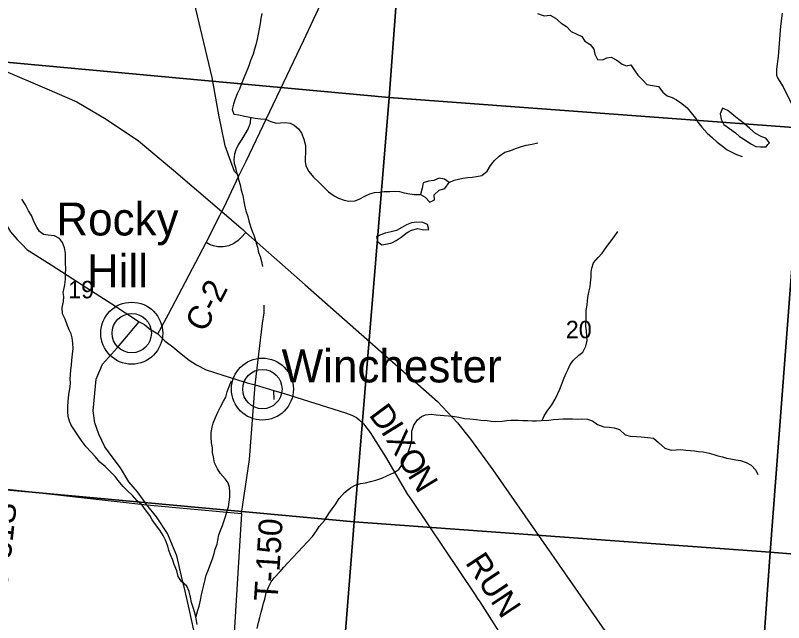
# Model space of a CAD drawing. Extents: x 1715311 to 2083412, y 146837 to 553079.
# Drawn here: x 1954235 to 1963973, y 356508 to 364200 of the extents above; entities that cross this region are included whole.
import ezdxf

# ---------------------------------------------------------------- set-up
doc = ezdxf.new("R2010")
doc.units = 0
for name, color, linetype in [('GM_X_County_Road', 7, 'Continuous'), ('GM_X_County_Road_Text', 7, 'Continuous'), ('GM_X_Minor_Lake', 7, 'Continuous'), ('GM_X_Minor_River', 7, 'Continuous'), ('GM_X_Section', 7, 'Continuous'), ('GM_X_Section_Text', 7, 'Continuous'), ('GM_X_State_Route', 7, 'Continuous'), ('GM_X_Township_Road', 7, 'Continuous'), ('GM_X_Township_Road_Text', 7, 'Continuous'), ('GM_X_Township_ROW', 7, 'Continuous'), ('GM_X_Township_Subdivision', 7, 'Continuous'), ('GM_X_Unincorporated', 7, 'Continuous'), ('GM_X_Unincorporated_Location', 7, 'Continuous'), ('GM_X_Unincorporated_Text', 7, 'Continuous'), ('GM_X_US_Route', 7, 'Continuous')]:
    doc.layers.add(name, color=color, linetype=linetype)

msp = doc.modelspace()

# ---------------------------------------------------------------- linework, layer by layer
at = {"layer": 'GM_X_County_Road'}
for points in [[(1953324, 363823.9), (1953334.1, 363699.1), (1953343.2, 363599.2), (1953386.3, 363492.5), (1953440.8, 363394.8), (1953482.8, 363304), (1953627.9, 362731.6), (1953678, 362472.8), (1953734.7, 362326), (1954079.4, 361615.9), (1954175, 361456.6), (1954259.1, 361358.7), (1954329.7, 361290.4), (1954382, 361233.5), (1954689.1, 361040.1), (1955096.4, 360778.3), (1955455.9, 360546.2), (1955806.2, 360315.7)], [(1956041.5, 360166.1), (1956175.7, 360414.7), (1956652.1, 361322.2)], [(1956496.9, 356413.5), (1956435.8, 356683.5), (1956388.9, 356905.5), (1956342.2, 357095.5), (1956283.2, 357353.5), (1956162.1, 357635.2), (1956025.4, 357848.8), (1955900.2, 358001.2), (1955782.3, 358163.9), (1955673.9, 358289.5), (1955567.3, 358467.2), (1955462.9, 358608.9), (1955370.4, 358736.5), (1955293.8, 358894.3), (1955243.3, 359040.2), (1955220.7, 359190.3), (1955260.9, 359590.9), (1955338, 359781.5), (1955528.9, 359994.7), (1955806.2, 360315.7)], [(1955806.2, 360315.7), (1955870, 360282.7), (1955936, 360227.7), (1956041.5, 360166.1)], [(1956041.5, 360166.1), (1956133.9, 360071.6), (1956232.9, 359999), (1956338.4, 359913.2), (1956439.6, 359834), (1956531.9, 359774.5), (1956655.1, 359710.8), (1957048.8, 359583.1), (1957174.1, 359543.5), (1957275.3, 359519.4), (1957509.3, 359448.8), (1957640.4, 359409.4), (1958420.2, 359165.6), (1958501.2, 359136.5), (1958557.8, 359104), (1958593.5, 359074.9), (1958646.9, 359026.3), (1958731.1, 358916.2), (1958927, 358606.8), (1959206.2, 358129.1), (1959222.5, 358108), (1959266.6, 358042.4), (1960062.6, 356859.4), (1960089.4, 356819.1), (1960120.3, 356770.8), (1960802.6, 355702.6)], [(1955900.2, 358001.2), (1957100.4, 357888.1), (1957201, 358574.4), (1957275.3, 359519.4)], [(1953288.4, 358290.3), (1953525.5, 358265.5), (1953751.8, 358240.9), (1955900.2, 358001.2)]]:
    msp.add_lwpolyline(points, dxfattribs=at)
at = {"layer": 'GM_X_Minor_Lake'}
for points in [[(1963197.6, 363024.8), (1963167.7, 362950.7), (1963179.7, 362884.6), (1963215.6, 362818.6), (1963285.5, 362768.6), (1963361.3, 362712.6), (1963415.1, 362666.6), (1963488.9, 362620.6), (1963554.8, 362574.5), (1963618.6, 362540.5), (1963680.4, 362534.5), (1963750.2, 362534.6), (1963773.5, 362563.4)], [(1963773.5, 362563.4), (1963792.1, 362586.6), (1963748.2, 362644.6), (1963696.3, 362662.6), (1963616.5, 362702.6), (1963544.7, 362766.7), (1963476.9, 362824.7), (1963405.1, 362878.7), (1963339.2, 362932.7), (1963263.4, 362994.8), (1963197.6, 363024.8)], [(1959734.9, 362082.2), (1959672.2, 362125.2), (1959606.4, 362137.1), (1959540.6, 362109.1), (1959470.8, 362099.1), (1959403, 362079.1), (1959393.1, 362011), (1959371, 361929.7)], [(1959371, 361929.7), (1959428.7, 361897.4), (1959488.3, 361835.1), (1959546.3, 361864.8), (1959544.6, 361926.9), (1959604.7, 361986.7), (1959676.7, 362008.4), (1959734.9, 362082.2)], [(1959209.8, 361451.7), (1959257.7, 361478.6), (1959335.5, 361500.6), (1959407.3, 361484.6), (1959475.1, 361486.7), (1959459.1, 361550.7), (1959401.2, 361576.7), (1959325.5, 361580.7), (1959257.7, 361570.7), (1959191.9, 361546.6), (1959134, 361512.6), (1959064.3, 361474.5), (1958998.5, 361456.5), (1958920.7, 361442.5), (1958813, 361398.4)], [(1958813, 361398.4), (1958823, 361334.4), (1958880.9, 361292.4), (1958950.7, 361304.4), (1959004.5, 361318.4), (1959062.3, 361346.5), (1959136.1, 361400.5), (1959189.9, 361440.6), (1959209.8, 361451.7)]]:
    msp.add_lwpolyline(points, dxfattribs=at)
at = {"layer": 'GM_X_Minor_River'}
for points in [[(1957357.5, 364225.2), (1957345.2, 364158.6), (1957338.9, 364096.6), (1957324.6, 364028.6), (1957314.4, 363960.6), (1957300.1, 363896.6), (1957281.9, 363828.6), (1957265.7, 363770.6), (1957249.4, 363708.7), (1957213.2, 363626.8), (1957197, 363572.8), (1957176.8, 363518.9), (1957154.6, 363466.9), (1957130.4, 363409), (1957096.1, 363325.1), (1957073.9, 363265.1), (1957047.7, 363207.2), (1957017.4, 363129.3), (1957001.2, 363075.3), (1956981, 363005.3), (1957002.7, 362947.2), (1957066.5, 362938.9), (1957138.3, 362924.6), (1957208.1, 362908.2), (1957273.9, 362897.9), (1957343.7, 362889.6), (1957403.5, 362883.3), (1957471.2, 362857), (1957539, 362832.7), (1957594.9, 362836.4), (1957652.8, 362842.2), (1957718.6, 362833.9), (1957770.4, 362807.6), (1957822.1, 362763.3), (1957859.7, 362709.1), (1957893.3, 362630.9), (1957912.9, 362552.8), (1957910.7, 362500.7), (1957910.1, 362350.6), (1957917.8, 362294.5), (1957953.4, 362220.3), (1958013, 362152), (1958078.6, 362089.6), (1958138.2, 362033.3), (1958203.7, 361963), (1958275.4, 361914.6), (1958331.1, 361884.3), (1958402.8, 361858), (1958460.7, 361845.7), (1958542.5, 361849.4), (1958602.5, 361877.1), (1958664.5, 361908.9), (1958726.5, 361938.6), (1958788.4, 361954.3), (1958856.3, 361962), (1958908.2, 361967.8), (1958982, 361969.5), (1959045.9, 361971.2), (1959105.8, 361966.9), (1959163.6, 361952.6), (1959233.4, 361938.3), (1959295.2, 361930), (1959371, 361929.7), (1959428.7, 361897.4), (1959488.3, 361835.1), (1959546.3, 361864.8), (1959544.6, 361926.9), (1959604.7, 361986.7), (1959676.7, 362008.4), (1959734.9, 362082.2), (1959794.9, 362111.9), (1959850.8, 362123.7), (1959906.7, 362137.4), (1959966.6, 362147.2), (1960026.5, 362150.9), (1960080.4, 362156.6), (1960148.3, 362170.4), (1960216.4, 362228.1), (1960258.6, 362300), (1960308.8, 362361.8), (1960368.9, 362417.5), (1960439, 362465.3), (1960514.9, 362489), (1960574.9, 362512.7), (1960636.8, 362536.4), (1960710.7, 362554.1), (1960784.7, 362569.8), (1960856.6, 362583.5)], [(1960851.8, 364222.7), (1960939.3, 364194.4), (1961015.2, 364204), (1961082.9, 364165.7), (1961152.5, 364099.3), (1961222.1, 364057), (1961279.7, 363996.7), (1961351.4, 363960.3), (1961415.2, 363934), (1961452.8, 363871.8), (1961520.5, 363831.5), (1961568.1, 363771.2), (1961579.8, 363707.1), (1961615.4, 363638.9), (1961681.3, 363638.6), (1961733.3, 363660.3), (1961787.2, 363670.1), (1961858.9, 363631.8), (1961926.5, 363581.4), (1961980.3, 363561.1), (1962034.2, 363574.9), (1962079.9, 363510.7), (1962125.5, 363442.4), (1962183.1, 363382.1), (1962240.7, 363323.8), (1962310.5, 363309.5), (1962386.3, 363297.1), (1962441.8, 363228.8), (1962497.5, 363178.5), (1962561.3, 363160.2), (1962613, 363129.9), (1962680.7, 363081.6), (1962748.3, 363029.3), (1962801.9, 362965), (1962855.5, 362896.7), (1962883.2, 362846.5), (1962936.8, 362782.2), (1963004.3, 362705.8), (1963071.9, 362647.5), (1963131.6, 362595.2), (1963197.2, 362542.8), (1963256.9, 362496.5), (1963308.6, 362470.3), (1963374.3, 362436), (1963446.1, 362411.6)], [(1957216.6, 362906.9), (1957211.7, 362832.2), (1957187.5, 362766.2), (1957143.3, 362696.3), (1957105.1, 362632.5), (1957056.9, 362560.6), (1957030.7, 362494.7), (1957014.5, 362442.7), (1957002.2, 362374.7), (1957010, 362324.7), (1957023.7, 362274.6), (1957033.5, 362224.5), (1957049.2, 362174.4), (1957065, 362122.3), (1957082.6, 362052.1), (1957098.3, 361984), (1957118, 361917.8), (1957131.6, 361841.7), (1957145.3, 361775.6), (1957155, 361723.5), (1957180.7, 361651.4), (1957194.4, 361595.2), (1957216, 361525.1), (1957235.8, 361467), (1957257.5, 361416.8), (1957273.2, 361364.7), (1957289, 361314.6), (1957302.7, 361262.5), (1957318.4, 361196.4), (1957336.1, 361144.3), (1957353.8, 361080.1), (1957367.5, 361020)], [(1954401.3, 361723.8), (1954361.7, 361798.1), (1954318.1, 361870.3)], [(1956539.8, 356484.1), (1956528.1, 356554.2), (1956514.4, 356616.4), (1956490.7, 356686.5), (1956469.1, 356762.7), (1956453.4, 356830.8), (1956435.8, 356900.9), (1956410.1, 356969.1), (1956340.6, 357029.5), (1956298.9, 357091.7), (1956281.3, 357163.8), (1956249.7, 357242), (1956230, 357298.2), (1956202.3, 357368.4), (1956180.6, 357424.5), (1956166.9, 357476.6), (1956137.3, 357550.8), (1956109.6, 357611), (1956066, 357679.2), (1956012.4, 357749.5), (1955970.8, 357811.8), (1955939.1, 357865.9), (1955885.5, 357936.2), (1955841.9, 357994.5), (1955778.2, 358050.8), (1955720.7, 358119.1), (1955651.1, 358181.5), (1955603.4, 358231.7), (1955537.9, 358308.1), (1955500.2, 358358.3), (1955432.6, 358426.6), (1955375, 358487), (1955307.4, 358541.3), (1955251.8, 358607.6), (1955192.2, 358671.9), (1955130.7, 358736.2), (1955067.2, 358818.6), (1954976, 358957.1), (1954940.3, 359009.3), (1954920.6, 359061.4), (1954902.8, 359119.6), (1954899.1, 359181.6), (1954901.4, 359247.7), (1954905.6, 359305.7), (1954909.9, 359359.7), (1954918.1, 359423.7), (1954928.4, 359493.7), (1954932.6, 359543.8), (1954930.8, 359593.8), (1954933.1, 359645.8), (1954939.3, 359707.9), (1954947.6, 359769.9), (1954951.8, 359833.9), (1954960.1, 359909.9), (1954966.4, 359978), (1954964.7, 360048), (1954953, 360114.1), (1954941.3, 360164.2), (1954915.6, 360218.4), (1954891.9, 360280.5), (1954866.3, 360350.7), (1954832.6, 360420.9), (1954829, 360501), (1954843.3, 360577), (1954847.5, 360637), (1954841.8, 360691.1), (1954858.1, 360765.1), (1954864.3, 360817.1), (1954870.5, 360867.1), (1954870.7, 360927.1), (1954873, 360989.2), (1954871.3, 361065.2), (1954871.6, 361133.3), (1954869.9, 361187.3), (1954858.2, 361255.5), (1954834.5, 361321.6), (1954794.8, 361371.8), (1954731.1, 361408.1), (1954651.3, 361414.5), (1954591.5, 361424.8), (1954539.8, 361463), (1954508.1, 361515.2), (1954474.5, 361579.4), (1954438.9, 361663.6), (1954401.3, 361723.8)], [(1960912.5, 359067.4), (1960935.4, 359126.4), (1960983.6, 359198.2), (1961035.8, 359268), (1961078, 359339.9), (1961110.2, 359409.8), (1961134.4, 359465.8), (1961164.7, 359539.7), (1961192.9, 359609.6), (1961217.1, 359665.5), (1961241.3, 359717.5), (1961267.5, 359777.4), (1961309.6, 359831.2), (1961377.8, 359897), (1961427.8, 359932.8), (1961466, 360008.7), (1961480.3, 360082.7), (1961476.6, 360138.7), (1961472.9, 360202.8), (1961467.1, 360262.9), (1961467.7, 360389), (1961470, 360461), (1961480.3, 360531), (1961486.5, 360587), (1961494.8, 360651), (1961507, 360709), (1961519.2, 360761), (1961525.4, 360813), (1961533.7, 360889.1), (1961534, 360947.1), (1961540.2, 360999.1), (1961564.4, 361067.1), (1961620.6, 361130.9), (1961672.7, 361188.7), (1961722.9, 361258.5), (1961771.1, 361324.3), (1961823.3, 361394.1), (1961871.4, 361460)], [(1956523.6, 356574.4), (1956546.5, 356666.3), (1956564.7, 356718.2), (1956581, 356794.2), (1956595.2, 356858.2), (1956605.5, 356914.2), (1956621.7, 356984.2), (1956640, 357052.1), (1956654.2, 357110.1), (1956684.4, 357182), (1956712.7, 357260), (1956732.9, 357315.9), (1956753.2, 357381.9), (1956769.4, 357439.9), (1956793.6, 357501.8), (1956799.8, 357551.8), (1956814, 357617.8), (1956834.2, 357675.8), (1956860.5, 357739.7), (1956898.9, 357853.6), (1956921.1, 357923.6), (1956937.3, 357975.5), (1956945.6, 358035.5), (1956953.8, 358101.6), (1956954.1, 358163.6), (1956948.3, 358217.7), (1956930.6, 358277.8), (1956892.9, 358328), (1956831.4, 358402.3), (1956795.7, 358454.6), (1956760.1, 358532.8), (1956746.5, 358606.9), (1956734.7, 358661), (1956733, 358721), (1956721.3, 358785.1), (1956715.6, 358855.2), (1956715.9, 358915.3), (1956730.1, 358983.3), (1956742.3, 359035.2), (1956770.6, 359105.2), (1956806.8, 359183.1), (1956833, 359241), (1956871.2, 359310.9), (1956901.4, 359362.8), (1956921.6, 359430.8), (1956943.9, 359500.7), (1956976.1, 359568.6)], [(1957301.8, 356434.7), (1957316.1, 356508.7), (1957334.3, 356570.6), (1957348.6, 356640.6), (1957366.8, 356698.6), (1957381, 356752.6), (1957397.2, 356804.5), (1957415.5, 356886.5), (1957443.8, 356956.5), (1957478, 357022.3), (1957516.1, 357076.2), (1957590.3, 357156), (1957636.4, 357209.8), (1957688.6, 357265.6), (1957752.7, 357331.3), (1957816.9, 357399.1), (1957875, 357462.9), (1957937.2, 357530.7), (1957999.3, 357600.5), (1958051.5, 357672.3), (1958083.7, 357724.2), (1958153.8, 357801.9), (1958210.1, 357889.7), (1958248.3, 357947.6), (1958290.4, 358001.5), (1958338.6, 358079.3), (1958406.8, 358155), (1958482.9, 358216.8), (1958542.9, 358250.5), (1958608.9, 358268.2), (1958674.7, 358277.9), (1958734.7, 358295.7), (1958802.6, 358311.4), (1958878.6, 358339.1), (1958952.5, 358370.8), (1959028.5, 358406.4), (1959096.5, 358446.2), (1959138.7, 358512), (1959166.9, 358563.9), (1959205.1, 358633.8), (1959227.3, 358699.8), (1959243.5, 358751.7), (1959259.8, 358821.7), (1959258, 358877.8), (1959260.3, 358931.8), (1959284.6, 359009.8), (1959330.8, 359077.6), (1959382.8, 359119.4), (1959434.8, 359141.2), (1959506.7, 359148.9), (1959570.5, 359140.6), (1959668.2, 359130.1), (1959724.1, 359127.9), (1959776, 359121.6), (1959855.7, 359111.3), (1959929.5, 359094.9), (1959997.3, 359090.6), (1960081.1, 359082.2), (1960135, 359074), (1960214.8, 359069.6), (1960266.6, 359059.3), (1960324.4, 359055.1), (1960404.3, 359060.7), (1960464.2, 359068.5), (1960516.1, 359074.2), (1960607.9, 359073.8), (1960665.8, 359069.6), (1960729.6, 359067.3), (1960785.5, 359065), (1960841.4, 359064.8), (1960901.2, 359066.5), (1960995.1, 359074.1), (1961051, 359081.8), (1961118.8, 359085.5), (1961178.7, 359089.2), (1961234.6, 359091), (1961294.4, 359088.7), (1961358.3, 359086.4), (1961410.2, 359088.2), (1961488, 359085.8), (1961549.8, 359065.5), (1961613.4, 359019.2), (1961693.1, 358988.8), (1961761, 358984.5), (1961824.8, 358976.2), (1961892.5, 358951.9), (1961964.1, 358887.5), (1962027.9, 358871.2), (1962107.7, 358864.9), (1962167.5, 358860.6), (1962249.3, 358854.2), (1962321.1, 358843.9), (1962386.7, 358787.5)], [(1962386.7, 358787.5), (1962468.3, 358719.1), (1962546, 358692.7), (1962609.8, 358696.5), (1962665.7, 358700.2), (1962733.6, 358693.9), (1962789.4, 358687.6), (1962841.3, 358683.4), (1962893.1, 358677.1), (1962953, 358672.9), (1963030.7, 358652.5), (1963088.5, 358638.2), (1963140.3, 358622), (1963196.1, 358605.7), (1963250, 358591.5), (1963303.8, 358581.2), (1963365.6, 358570.9), (1963425.4, 358560.6), (1963499.2, 358536.3), (1963562.9, 358504), (1963620.5, 358437.7), (1963646.2, 358383.5)]]:
    msp.add_lwpolyline(points, dxfattribs=at)
at = {"layer": 'GM_X_Section'}
for points in [[(1952754.9, 369183.8), (1959375.5, 368573.3), (1958974.7, 363158.1), (1952234.1, 363778.4), (1952509.1, 366607.6)], [(1959375.5, 368573.3), (1964620, 368129.6), (1964211.2, 362770.7), (1958974.7, 363158.1)], [(1952234.1, 363778.4), (1958974.7, 363158.1), (1958529.2, 357783.6), (1951688.6, 358412.1), (1951966.4, 361232.3)], [(1958974.7, 363158.1), (1964211.2, 362770.7), (1963799.8, 357398.1), (1958529.2, 357783.6)], [(1964211.2, 362770.7), (1969556.4, 362397.9), (1969150.3, 356964.7), (1963799.8, 357398.1)], [(1958529.2, 357783.6), (1958107.7, 352465.1), (1951153, 353047.6), (1951386.6, 355501.9), (1951688.6, 358412.1)], [(1963799.8, 357398.1), (1963420.2, 352039.6), (1958107.7, 352465.1), (1958529.2, 357783.6)], [(1963799.8, 357398.1), (1969150.3, 356964.7), (1968750.1, 351653.6), (1963420.2, 352039.6)]]:
    msp.add_lwpolyline(points, close=True, dxfattribs=at)
at = {"layer": 'GM_X_State_Route'}
for points in [[(1957158.9, 362353.6), (1957891.4, 363887.2), (1958316.8, 364800.5), (1958792.8, 365787)], [(1956660.6, 361339.3), (1956824.5, 361665.9), (1956852.8, 361715.4), (1956879.7, 361771.9), (1957069.1, 362165.6), (1957158.9, 362353.6)], [(1957154.3, 361451.1), (1957097.4, 361384.5), (1957059.2, 361347.7), (1957002.6, 361308.1), (1956941.9, 361281.2), (1956869.8, 361267.1), (1956803.3, 361269.9), (1956745.4, 361281.2), (1956704.4, 361294), (1956652.1, 361322.2), (1956660.6, 361339.3)]]:
    msp.add_lwpolyline(points, dxfattribs=at)
at = {"layer": 'GM_X_Township_Road'}
for points in [[(1963953.6, 364227.3), (1963934.5, 364064), (1963904.7, 363679), (1963883.2, 363516.9), (1963882, 363471.5), (1963883.2, 363444.2), (1963895.2, 363407.2), (1963966.6, 363296.3), (1964094.2, 363037.7)], [(1957069.1, 362165.6), (1957011.9, 362222.7), (1956965.1, 362350.1), (1956894.4, 362546.3), (1956837.8, 362815.4), (1956819.9, 362912.5)], [(1957275.3, 359519.4), (1957365.4, 360298.1), (1957387.5, 360432.3), (1957389.7, 360526.9)], [(1957100.4, 357888.1), (1956997.3, 356169.6), (1957184.3, 355870.2), (1957399.3, 355585), (1957521.8, 355433.4), (1957660.2, 355289.9), (1958014.6, 355095.4), (1958535.3, 354771.5), (1959068, 354455.8), (1959698.8, 354074.4), (1960199.6, 353752.4), (1960538, 353553.8), (1960710.2, 353462.5), (1960966.9, 353223.5), (1961113.2, 353104.1), (1961391.9, 352863.2), (1961771.6, 352642.7)]]:
    msp.add_lwpolyline(points, dxfattribs=at)
at = {"layer": 'GM_X_Township_ROW'}
msp.add_lwpolyline([(1956819.9, 362912.5), (1956727.4, 363413.2), (1956415.4, 364731.5)], dxfattribs=at)
at = {"layer": 'GM_X_Township_Subdivision'}
msp.add_lwpolyline([(1957513.7, 359335.6), (1957509.3, 359448.8)], dxfattribs=at)
at = {"layer": 'GM_X_Unincorporated'}
for centre, radius in [((1955709.7, 360173.7), 392.8), ((1955709.7, 360173.7), 249), ((1957366.2, 359465.8), 392.8), ((1957366.2, 359465.8), 249)]:
    msp.add_circle(centre, radius, dxfattribs=at)
at = {"layer": 'GM_X_Unincorporated_Location'}
for p, q in [((1955709.7, 360173.7), (1955709.7, 360173.7)), ((1957366.2, 359465.8), (1957366.2, 359465.8))]:
    msp.add_line(p, q, dxfattribs=at)
at = {"layer": 'GM_X_US_Route'}
for points in [[(1953596.2, 363706.8), (1953714, 363656.2), (1954078.7, 363506.1), (1954632.7, 363267.6), (1955016, 363103.5), (1955386.9, 362886.7), (1955795.3, 362611.6), (1956241.2, 362240.6), (1956852.8, 361715.4), (1957096, 361506.1), (1957116.1, 361487.1)], [(1957116.1, 361487.1), (1957154.3, 361451.1), (1957906.5, 360788.2)], [(1957906.5, 360788.2), (1959585.5, 359308.8), (1959840.1, 359038.3), (1960004.4, 358829.9), (1960287.7, 358444.8), (1961802.7, 356263), (1962101.5, 355891), (1962595.4, 355487.7), (1965246.1, 354501.5)]]:
    msp.add_lwpolyline(points, dxfattribs=at)

# ---------------------------------------------------------------- texts
at = {"layer": 'GM_X_County_Road_Text'}
for s, rotation, p in [('C-2', 62.41247, (1956637.8, 360171.7)), ('D', 306.64551, (1958707, 359136.9)), ('I', 301.78445, (1958860.8, 358930.7)), ('X', 301.33736, (1958925.3, 358826.5)), ('O', 301.31111, (1959062.6, 358601)), ('N', 301.50333, (1959200.4, 358374.6)), ('RUN', 303.50986, (1959930.6, 357266.4))]:
    msp.add_text(s, height=300, rotation=rotation, dxfattribs=at).set_placement(p)
at = {"layer": 'GM_X_Section_Text'}
for s, p in [('19', (1954904.2, 360615.8)), ('20', (1961211.6, 360109.8))]:
    msp.add_text(s, height=221, rotation=0.00001, dxfattribs=at).set_placement(p)
at = {"layer": 'GM_X_Township_Road_Text'}
for s, rotation, p in [('T-31S', 83.66003, (1954133, 356927.9)), ('T-150', 86.35356, (1957557.8, 356771.9))]:
    msp.add_text(s, height=300, rotation=rotation, dxfattribs=at).set_placement(p)
at = {"layer": 'GM_X_Unincorporated_Text'}
for s, p in [('Rocky', (1954754.6, 361411.6)), ('Hill', (1955141.8, 360756)), ('Winchester', (1957610.2, 359550.4))]:
    msp.add_text(s, height=417, rotation=0.00001, dxfattribs=at).set_placement(p)

doc.saveas('drawing.dxf')
